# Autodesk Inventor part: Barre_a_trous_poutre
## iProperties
Shininess: 64.0
Length Units: 11269
Angle Units: 11279
Time Units: 11290
Mass Units: 11283
Length Display Precision: 3
Angle Display Precision: 2
Compacted: True
Part Number: Barre_a_trous_poutre
Document SubType Name: Modeling
Created: 2008-04
Material: Par défaut
Designer: Pascal
Density: 0.0
Volumn: 0.0
Area: 0.0
PropertySet Name: Model Information
Control State: 0
Master: False
Checked Out: False
DESIGNATION: pièce
Author: Pascal
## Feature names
1. Extrusion1
2. Chanfrein1 [Chamfer]
3. Extrusion2
4. Réseau rectangulaire3 [Rectangular Pattern]
5. Extrusion3
